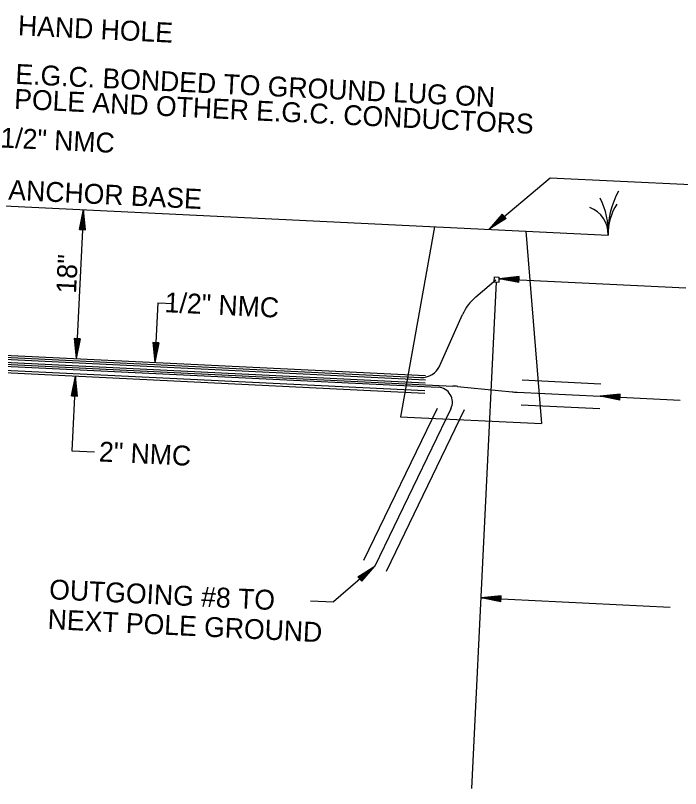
# Model space of a CAD drawing. Extents: x 661018 to 663325, y 642537 to 643074.
# Drawn here: x 661753.3 to 661866, y 642729.7 to 642860.7 of the extents above; entities that cross this region are included whole.
import ezdxf

# ---------------------------------------------------------------- set-up
doc = ezdxf.new("R2010")
doc.units = 0
doc.layers.add('R_Dimension', color=7, linetype='Continuous')

msp = doc.modelspace()

# ---------------------------------------------------------------- linework, layer by layer
at = {"layer": 'R_Dimension'}
for p, q in [((661833.54, 642824.44), (661843.89, 642833.18)), ((661843.89, 642833.18), (661867.7, 642832.03)), ((661675.86, 642832.09), (661853.7, 642823.46)), ((661764.78, 642827.77), (661763.55, 642802.53)), ((661764.11, 642824.43), (661764.78, 642827.77)), ((661765.12, 642824.38), (661764.78, 642827.77)), ((661764.19, 642824.43), (661764.75, 642827.21)), ((661764.28, 642824.43), (661764.72, 642826.63)), ((661764.95, 642824.39), (661764.72, 642826.63)), ((661765.03, 642824.39), (661764.75, 642827.21)), ((661835.76, 642827.02), (661833.54, 642824.44)), ((661836.42, 642826.26), (661833.54, 642824.44)), ((661835.81, 642826.96), (661833.96, 642824.8)), ((661836.36, 642826.32), (661833.96, 642824.8)), ((661835.87, 642826.89), (661834.4, 642825.18)), ((661836.31, 642826.39), (661834.4, 642825.18)), ((661835.92, 642826.83), (661834.83, 642825.55)), ((661836.25, 642826.45), (661834.83, 642825.55)), ((661835.98, 642826.76), (661835.26, 642825.92)), ((661836.19, 642826.52), (661835.26, 642825.92)), ((661836.03, 642826.7), (661835.68, 642826.29)), ((661836.14, 642826.58), (661835.68, 642826.29)), ((661836.42, 642826.26), (661835.76, 642827.02)), ((661764.36, 642824.42), (661764.69, 642826.07)), ((661764.45, 642824.42), (661764.67, 642825.5)), ((661764.53, 642824.41), (661764.64, 642824.94)), ((661764.69, 642824.41), (661764.64, 642824.94)), ((661764.78, 642824.4), (661764.67, 642825.5)), ((661764.86, 642824.4), (661764.69, 642826.07)), ((661764.11, 642824.43), (661765.12, 642824.38)), ((661824.3, 642824.88), (661818.52, 642792.68)), ((661839.78, 642824.13), (661842.41, 642791.52)), ((661831.28, 642813), (661834.69, 642815.89)), ((661834.38, 642816.41), (661834.34, 642815.54)), ((661834.38, 642816.41), (661835.25, 642816.36)), ((661835.21, 642815.49), (661835.25, 642816.36)), ((661838.63, 642816.42), (661835.24, 642816.07)), ((661835.24, 642816.07), (661866.85, 642814.54)), ((661838.58, 642815.41), (661835.24, 642816.07)), ((661838.62, 642816.33), (661835.8, 642816.05)), ((661838.58, 642815.49), (661835.8, 642816.05)), ((661838.62, 642816.25), (661836.38, 642816.02)), ((661838.59, 642815.58), (661836.38, 642816.02)), ((661838.61, 642816.16), (661836.94, 642815.99)), ((661838.59, 642815.66), (661836.94, 642815.99)), ((661838.61, 642816.08), (661837.51, 642815.96)), ((661838.59, 642815.75), (661837.51, 642815.96)), ((661838.61, 642815.99), (661838.07, 642815.94)), ((661838.6, 642815.83), (661838.07, 642815.94)), ((661838.58, 642815.41), (661838.63, 642816.42)), ((661830.61, 642729.69), (661834.77, 642815.52)), ((661834.34, 642815.54), (661835.21, 642815.49)), ((661777.4, 642811.99), (661776.9, 642801.89)), ((661777.4, 642811.99), (661780.07, 642811.86)), ((661825.16, 642801.34), (661829.04, 642810.01)), ((661763.21, 642805.92), (661763.55, 642802.53)), ((661764.22, 642805.88), (661763.21, 642805.92)), ((661763.29, 642805.92), (661763.58, 642803.1)), ((661763.38, 642805.92), (661763.61, 642803.68)), ((661763.46, 642805.91), (661763.63, 642804.24)), ((661763.55, 642805.91), (661763.66, 642804.81)), ((661764.22, 642805.88), (661763.55, 642802.53)), ((661764.13, 642805.88), (661763.58, 642803.1)), ((661764.05, 642805.88), (661763.61, 642803.68)), ((661763.97, 642805.89), (661763.63, 642804.24)), ((661763.64, 642805.9), (661763.69, 642805.37)), ((661763.88, 642805.89), (661763.66, 642804.81)), ((661763.79, 642805.9), (661763.69, 642805.37)), ((661776.56, 642805.28), (661776.9, 642801.89)), ((661777.57, 642805.23), (661776.56, 642805.28)), ((661776.65, 642805.27), (661776.93, 642802.45)), ((661776.73, 642805.27), (661776.96, 642803.03)), ((661776.82, 642805.26), (661776.99, 642803.59)), ((661776.9, 642805.26), (661777.02, 642804.16)), ((661777.57, 642805.23), (661776.9, 642801.89)), ((661777.49, 642805.23), (661776.93, 642802.45)), ((661777.4, 642805.24), (661776.96, 642803.03)), ((661776.99, 642805.26), (661777.04, 642804.72)), ((661777.32, 642805.24), (661776.99, 642803.59)), ((661777.23, 642805.24), (661777.02, 642804.16)), ((661777.15, 642805.25), (661777.04, 642804.72)), ((661739.5, 642803), (661822.74, 642798.96)), ((661739.51, 642803.35), (661821.92, 642799.35)), ((661739.53, 642803.7), (661822.77, 642799.66)), ((661739.44, 642801.82), (661824.9, 642797.67)), ((661739.45, 642802.16), (661827.36, 642797.89)), ((661739.47, 642802.5), (661822.71, 642798.45)), ((661739.39, 642800.74), (661822.63, 642796.7)), ((661739.41, 642801.16), (661822.65, 642797.12)), ((661762.74, 642796.24), (661763.41, 642799.58)), ((661763.41, 642799.58), (661762.79, 642786.93)), ((661762.82, 642796.23), (661763.38, 642799.01)), ((661763.66, 642796.19), (661763.38, 642799.01)), ((661763.75, 642796.19), (661763.41, 642799.58)), ((661839.16, 642798.92), (661852.47, 642798.27)), ((661762.91, 642796.23), (661763.35, 642798.44)), ((661762.99, 642796.22), (661763.32, 642797.88)), ((661763.49, 642796.2), (661763.32, 642797.88)), ((661763.58, 642796.19), (661763.35, 642798.44)), ((661828.2, 642797.83), (661837.42, 642796.92)), ((661762.74, 642796.24), (661763.75, 642796.19)), ((661763.08, 642796.22), (661763.3, 642797.3)), ((661763.16, 642796.21), (661763.27, 642796.74)), ((661763.32, 642796.21), (661763.27, 642796.74)), ((661763.41, 642796.2), (661763.3, 642797.3)), ((661838.26, 642796.86), (661852.37, 642796.17)), ((661855.76, 642796.51), (661852.37, 642796.17)), ((661852.37, 642796.17), (661865.93, 642795.51)), ((661855.71, 642795.5), (661852.37, 642796.17)), ((661855.76, 642796.43), (661852.93, 642796.14)), ((661855.72, 642795.59), (661852.93, 642796.14)), ((661855.75, 642796.34), (661853.51, 642796.11)), ((661855.75, 642796.26), (661854.07, 642796.09)), ((661855.74, 642796.17), (661854.64, 642796.06)), ((661855.71, 642795.5), (661855.76, 642796.51)), ((661855.72, 642795.67), (661853.51, 642796.11)), ((661855.72, 642795.76), (661854.07, 642796.09)), ((661855.73, 642795.84), (661854.64, 642796.06)), ((661855.74, 642796.09), (661855.2, 642796.03)), ((661855.73, 642795.93), (661855.2, 642796.03)), ((661824.74, 642794.09), (661812.27, 642768.3)), ((661827.05, 642794.05), (661814.17, 642767.39)), ((661829.31, 642793.87), (661816.06, 642766.47)), ((661838.95, 642794.71), (661852.27, 642794.07)), ((661818.52, 642792.68), (661842.41, 642791.52)), ((661762.79, 642786.93), (661766.67, 642786.74)), ((661814.17, 642767.39), (661807.16, 642761.32)), ((661811.29, 642765.57), (661814.17, 642767.39)), ((661811.95, 642764.8), (661814.17, 642767.39)), ((661811.34, 642765.5), (661813.74, 642767.02)), ((661811.4, 642765.44), (661813.3, 642766.64)), ((661811.45, 642765.37), (661812.88, 642766.27)), ((661811.78, 642764.99), (661812.88, 642766.27)), ((661811.84, 642764.93), (661813.3, 642766.64)), ((661811.89, 642764.87), (661813.74, 642767.02)), ((661811.29, 642765.57), (661811.95, 642764.8)), ((661811.51, 642765.31), (661812.45, 642765.9)), ((661811.57, 642765.24), (661812.02, 642765.53)), ((661811.67, 642765.12), (661812.02, 642765.53)), ((661811.73, 642765.06), (661812.45, 642765.9)), ((661835.56, 642762.33), (661832.17, 642761.98)), ((661835.56, 642762.24), (661832.74, 642761.96)), ((661835.56, 642762.16), (661833.32, 642761.93)), ((661835.55, 642762.07), (661833.88, 642761.9)), ((661835.52, 642761.32), (661835.56, 642762.33)), ((661803.28, 642761.51), (661807.16, 642761.32)), ((661832.17, 642761.98), (661864.22, 642760.43)), ((661835.52, 642761.32), (661832.17, 642761.98)), ((661835.52, 642761.4), (661832.74, 642761.96)), ((661835.52, 642761.49), (661833.32, 642761.93)), ((661835.53, 642761.57), (661833.88, 642761.9)), ((661835.55, 642761.99), (661834.45, 642761.87)), ((661835.53, 642761.66), (661834.45, 642761.87)), ((661835.54, 642761.9), (661835.01, 642761.85)), ((661835.54, 642761.74), (661835.01, 642761.85))]:
    msp.add_line(p, q, dxfattribs=at)
for centre, radius, start, end in [((661867.87, 642824.01), 14.19, 150.8235, 182.237), ((661840.82, 642823.99), 12.89, 357.6269, 26.4493), ((661848.82, 642823.61), 4.88, 358.2316, 68.4339), ((661862.66, 642823.75), 8.97, 146.3648, 181.8916), ((661836.73, 642806.57), 8.42, 130.2817, 155.9249), ((661822.09, 642802.71), 3.37, 267.2199, 335.9249), ((661824.78, 642795.15), 2.53, 334.2039, 87.2199), ((661826.55, 642781.06), 16.85, 84.3531, 87.2199), ((661839.08, 642813.68), 16.85, 264.3531, 267.2199)]:
    msp.add_arc(centre, radius, start, end, dxfattribs=at)

# ---------------------------------------------------------------- texts
for s, height, rotation, p in [('HAND HOLE', 3.369, 357.2199, (661753.63, 642857.33)), ('E.G.C. BONDED TO GROUND LUG ON ', 3.3692, 357.2199, (661753.19, 642849.1)), ('POLE AND OTHER E.G.C. CONDUCTORS', 3.3692, 357.2199, (661752.99, 642844.88)), (' 1/2" NMC ', 3.369, 357.2199, (661749.4, 642838.38)), ('ANCHOR BASE', 3.3692, 357.2199, (661752, 642829.47)), ('18"', 3.369, 87.2199, (661763.52, 642813.5)), (' 1/2" NMC ', 3.369, 357.2199, (661777.24, 642810.47)), ('2" NMC', 3.369, 357.2199, (661767.35, 642785.12)), ('OUTGOING #8 TO', 3.3692, 357.2199, (661758.91, 642761.78)), ('NEXT POLE GROUND', 3.3692, 357.2199, (661758.66, 642756.73))]:
    msp.add_text(s, height=height, rotation=rotation, dxfattribs=at).set_placement(p)

doc.saveas('drawing.dxf')
